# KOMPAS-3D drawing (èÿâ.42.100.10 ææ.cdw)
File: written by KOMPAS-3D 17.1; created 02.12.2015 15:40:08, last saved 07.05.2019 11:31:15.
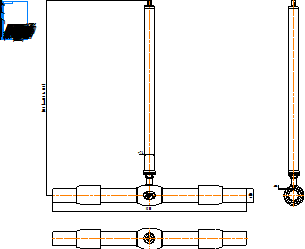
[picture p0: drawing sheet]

Sheet 1: A4, portrait

Title block, sheet 1: name: КШГ.42.100.10 СС; material: Внимание! Данный продукт является объектом авторского права ООО «Торговый Дом АДЛ». / Запрещается изменение, копирование, распространение / (в том числе путем копирования на другие сайты и ресурсы в Интернете) / или любое иное использование информации и объектов без предварительного / согласия правообладателя (ООО «Торговый Дом АДЛ»).; sheets: 1; organisation: ООО "Торговый дом АДЛ"; sheet format: A4; stored path: C:\Users\kka\KOMPAS_Work\Модели кранов для исследований\DN50\С удлинением\КШГ.32.050.40 СС ГЧ _ Шаровой кран БИВАЛ Ду50 Ру4 МПа редуцированный под приварку, с удлинением штока H=1100.cdw; drawn by: Климкович К.А.; drawn by, date: 02.12.15

Views: Вид 1, Проекционный вид 2
Referenced files in C:\Users\kka\KOMPAS_Work\Модели кранов для исследований\DN80\С удлинением\: КШТ.22.080.25 СС.a3d, КШГ.35.065.25 СС.a3d!КШГ.45.065.10 СС!Деталь (локальная).m3d
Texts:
  Klimkovich
  ADL
  (от 380 до 5000)
Dimensions and other numbers on the sheet: 1500; 110; 76; 10; 1:1; 1; 02.12.15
